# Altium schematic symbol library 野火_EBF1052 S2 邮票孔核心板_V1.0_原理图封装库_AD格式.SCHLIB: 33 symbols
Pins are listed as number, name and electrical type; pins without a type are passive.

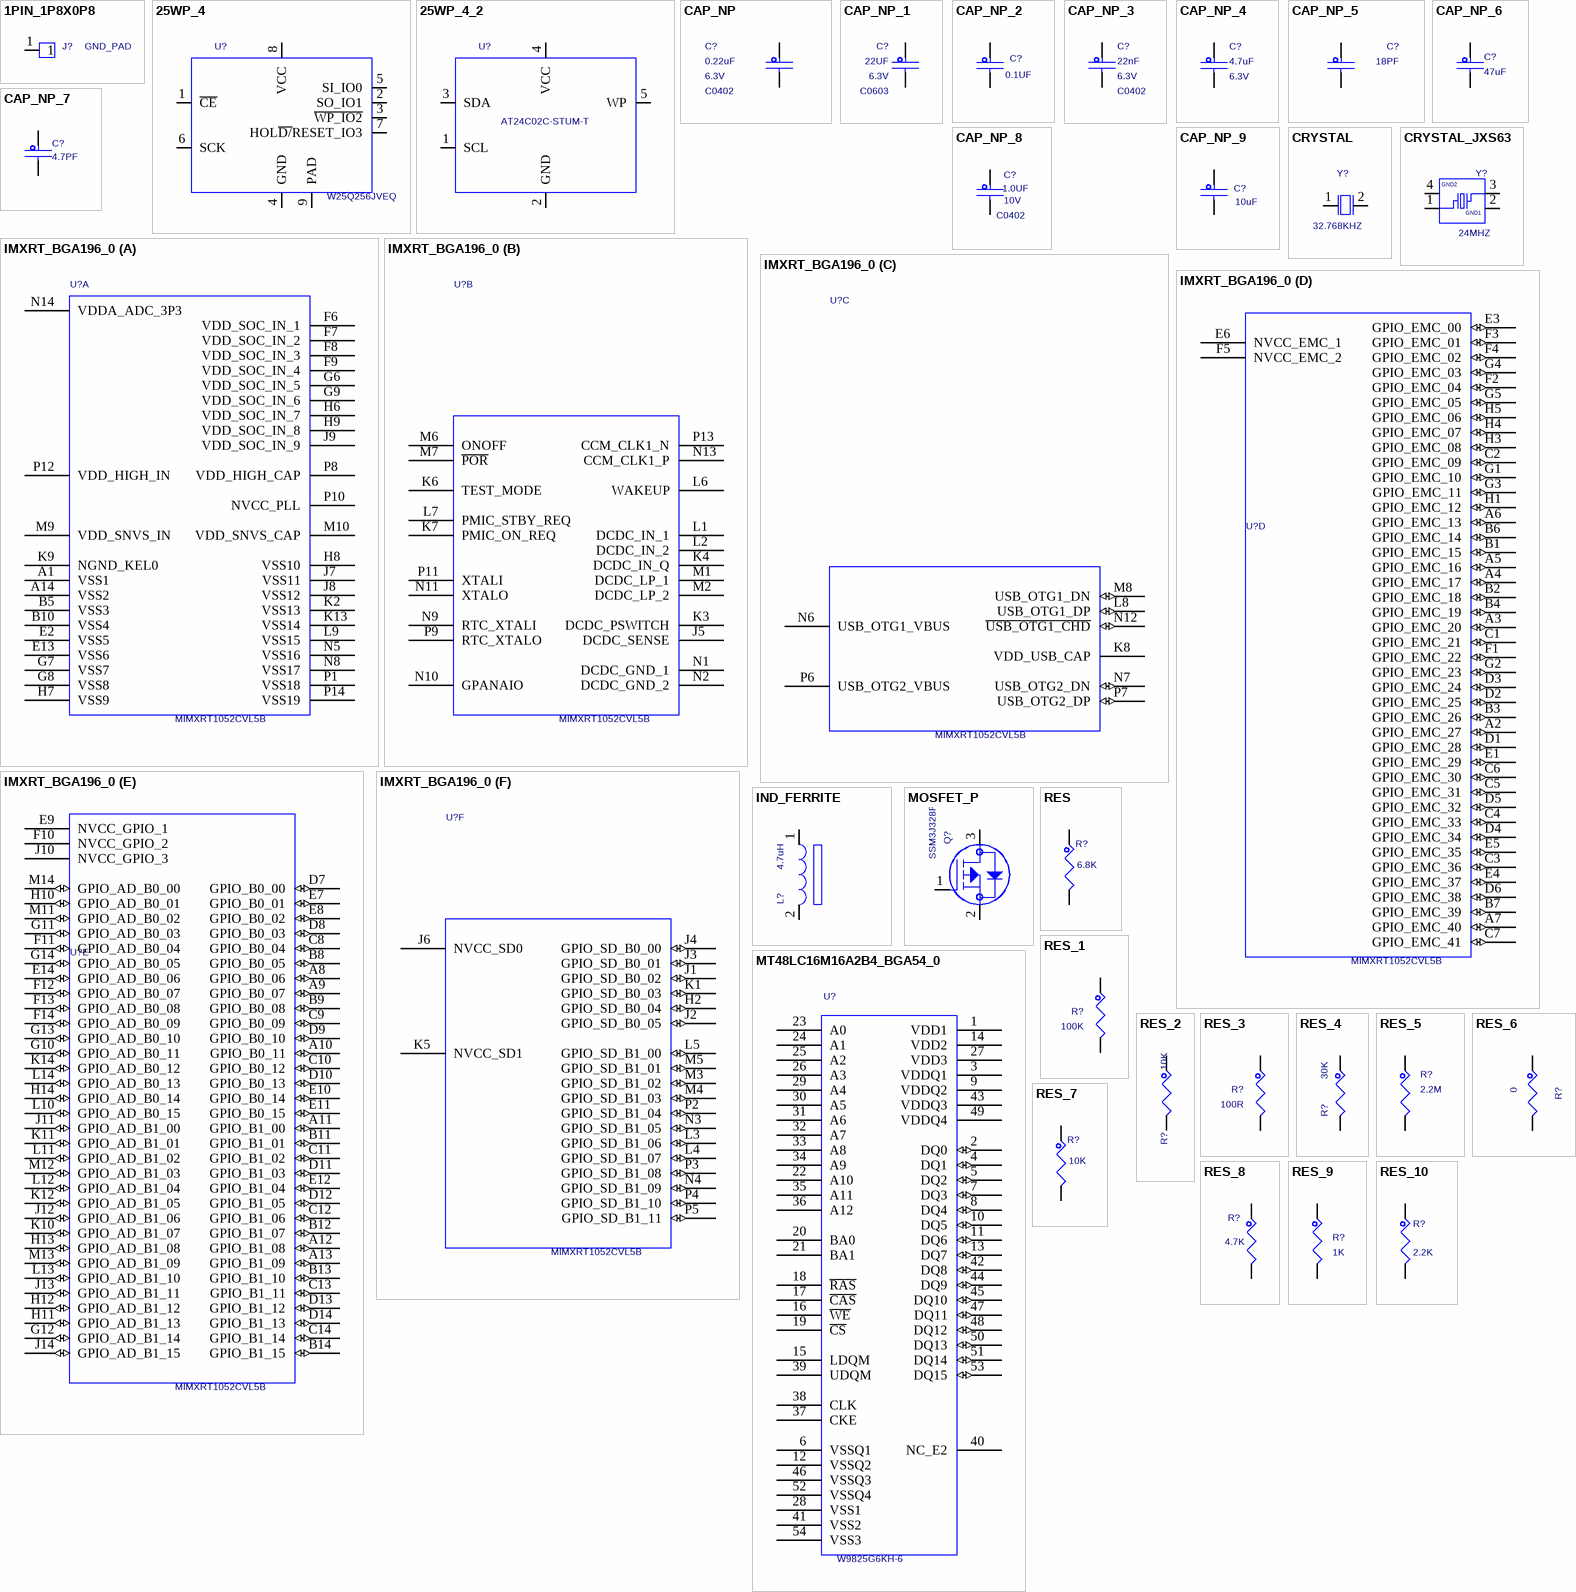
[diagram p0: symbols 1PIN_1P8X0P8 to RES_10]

## 1PIN_1P8X0P8
designator J?  value GND_PAD  (hidden comment: 1PIN_1P8X0P8)
PCB DECAL: PIN-SMD2X2; Source_Path: D:\NXP_RT1050\RT1050_MB_PRO\SCH\LIBRARY1.OLB
footprint PIN-SMD2X2
pins: 1

## 25WP_4
designator U?  value W25Q256JVEQ  (hidden comment: 25WP_4)
IC MEM FLASH QPI 64Mb 1.65-1.95V SOIC8W; PCB DECAL: WSON8_8X6; AGILE_PN: 334-77734; MFG_NAME01: ISSI; MFG_PN01: IS25WP064A-JBLE; Temp_Range: -40C to +105C; CAD_APPROVED: Yes; Source_Path: F:\STM32\F429\SCH\V4\CORE\STM32H743_CORE\STM32H743_CORE.DSN
footprint WSON8_8X6
pins: 1 ~{CE}, 2 SO_IO1, 3 ~{WP_IO2}, 4 GND (power), 5 SI_IO0, 6 SCK, 7 HOL~{D/}RESET_IO3, 8 VCC (power), 9 PAD (power)

## 25WP_4_2
designator U?  value AT24C02C-STUM-T  (hidden comment: 25WP_4_2)
IC MEM FLASH QPI 64Mb 1.65-1.95V SOIC8W; AGILE_PN: 334-77734; MFG_NAME01: ISSI; MFG_PN01: IS25WP064A-JBLE; Temp_Range: -40C to +105C; CAD_APPROVED: Yes; PCB DECAL: SOT23-5; Source_Path: D:\NXP_RT1050\SCH\RT1052B_CORE\IMXRT1052_180613.DSN
footprint SOT23-5
pins: 1 SCL, 2 GND, 3 SDA, 4 VCC (power), 5 WP

## CAP_NP
designator C?  value 0.22uF  VOLTAGE: 6.3V  PCB DECAL: C0402  (hidden comment: CAP_NP)
CAP CER 0.22UF 6.3V 20% X5R 0402; FPLIST: CC0402_25,CC0402_HD,0402_CC; CAD_APPROVED: Yes; MFG_PN01: C0402C224M9PAC; MFG_NAME01: KEMET; AGILE_PN: 150-76271; Source_Path: Q:\ORCADCIS\SYMBOLS\FCL_CAPACITOR.OLB; CLASS: DISCRETE
footprint C0402
pins: 1, 2

## CAP_NP_1
designator C?, comment value 22UF  PCB DECAL: C0603  voltage_rating: 6.3V  (hidden comment: CAP_NP)
CAP CER 22UF 6.3V 20% X5R 0603; FPLIST: CC0603_OV,CC0603,0603_CC; CAD_APPROVED: Yes; MFG_PN01: CL10A226MQ8NRNE; MFG_NAME01: Samsung; AGILE_PN: 150-78467; Source_Path: Q:\ORCADCIS\SYMBOLS\FCL_CAPACITOR.OLB; CLASS: DISCRETE
footprint C0603
pins: 1, 2

## CAP_NP_2
designator C?, comment value 0.1UF  (hidden comment: CAP_NP)
CAP CER 0.1UF 10V 10% X5R 0402; PCB DECAL: C0402; AGILE_PN: 150-75634; MFG_NAME01: KEMET; MFG_PN01: C0402C104K8PAC; CAD_APPROVED: Yes; FPLIST: CC0402_25,CC0402_HD,0402_CC; Source_Path: Q:\ORCADCIS\SYMBOLS\FCL_CAPACITOR.OLB; CLASS: DISCRETE
footprint C0402
pins: 1, 2

## CAP_NP_3
designator C?, comment value 22nF  PCB DECAL: C0402  VOLTAGE: 6.3V  (hidden comment: CAP_NP)
CAP CER 0.22UF 6.3V 20% X5R 0402; AGILE_PN: 150-76271; MFG_NAME01: KEMET; MFG_PN01: C0402C224M9PAC; CAD_APPROVED: Yes; FPLIST: CC0402_25,CC0402_HD,0402_CC; Source_Path: Q:\ORCADCIS\SYMBOLS\FCL_CAPACITOR.OLB; CLASS: DISCRETE
footprint C0402
pins: 1, 2

## CAP_NP_4
designator C?, comment value 4.7uF  voltage_rating: 6.3V  (hidden comment: CAP_NP)
CAP CER 4.7UF 6.3V 20% X5R 0402; FPLIST: CC0402_25,CC0402_HD,0402_CC; CAD_APPROVED: Yes; MFG_PN01: C1005X5R0J475M050BC; MFG_NAME01: TDK; AGILE_PN: 150-78463; PCB DECAL: C0402; Source_Path: Q:\ORCADCIS\SYMBOLS\FCL_CAPACITOR.OLB; CLASS: DISCRETE
footprint C0402
pins: 1, 2

## CAP_NP_5
designator C?, comment value 18PF  (hidden comment: CAP_NP)
CAP CER 18PF 50V 1% C0G 0402; ROOM: ATLAS-AP; PRIORITY_PN: 021-00248; CAD_APPROVED: Yes; MFG_PN01: CC0402FRNPO9BN180; MFG_NAME01: YAGEO; AGILE_PN: 150-76630; FPLIST: CC0402_25,CC0402_HD,0402_CC; PCB DECAL: C0402; Source_Path: Q:\ORCADCIS\SYMBOLS\FCL_CAPACITOR.OLB; CLASS: DISCRETE
footprint C0402
pins: 1, 2

## CAP_NP_6
designator C?, comment value 47uF  (hidden comment: CAP_NP)
CAP CER 33UF 6.3V 20% X5R 1210; FPLIST: CC1210,1210_CC; CAD_APPROVED: Yes; MFG_PN01: GRM32DR60J336ME19L; MFG_NAME01: MURATA; AGILE_PN: 150-76796; PCB DECAL: C0805; Source_Path: Q:\ORCADCIS\SYMBOLS\FCL_CAPACITOR.OLB; CLASS: DISCRETE
footprint C0805
pins: 1, 2

## CAP_NP_7
designator C?, comment value 4.7PF  (hidden comment: CAP_NP)
CAP CER 4.7PF 50V 0.25PF C0G 0402; AGILE_PN: 150-76335; MFG_NAME01: MURATA; MFG_PN01: GRM1555C1H4R7CA01D; CAD_APPROVED: Yes; FPLIST: CC0402_25,CC0402_HD,0402_CC; PCB DECAL: C0402; Source_Path: Q:\ORCADCIS\SYMBOLS\FCL_CAPACITOR.OLB; CLASS: DISCRETE
footprint C0402
pins: 1, 2

## CAP_NP_8
designator C?, comment value 1.0UF  VOLTAGE: 10V  PCB DECAL: C0402  (hidden comment: CAP_NP)
CAP CER 1.0UF 10V 10% X5R 0402; FPLIST: CC0402_25,CC0402_HD,0402_CC; CAD_APPROVED: Yes; MFG_PN01: CC0402KRX5R6BB105; MFG_NAME01: YAGEO AMERICA; AGILE_PN: 150-75772; Source_Path: Q:\ORCADCIS\SYMBOLS\FCL_CAPACITOR.OLB; CLASS: DISCRETE
footprint C0402
pins: 1, 2

## CAP_NP_9
designator C?, comment value 10uF  (hidden comment: CAP_NP)
CAP CER 10UF 10V 10% X5R 0603; PCB DECAL: C0603; FPLIST: CC0603_OV,CC0603,0603_CC; CAD_APPROVED: Yes; MFG_PN01: C1608X5R1A106K; MFG_NAME01: TDK; AGILE_PN: 150-78675; Source_Path: Q:\ORCADCIS\SYMBOLS\FCL_CAPACITOR.OLB; CLASS: DISCRETE
footprint C0603
pins: 1, 2

## CRYSTAL
designator Y?  value 32.768KHZ  (hidden comment: CRYSTAL)
XTAL 32.768KHZ 7PF 20PPM -- SMT; CAD_APPROVED: Yes; MFG_PN01: FC-135 32.7680KA-AG3; MFG_NAME01: EPSON ELECTRONICS; AGILE_PN: 230-78102; PCB DECAL: 3215; Source_Path: Q:\ORCADCIS\SYMBOLS\FCL_XTAL_OSC.OLB; CLASS: IC
footprint 3215
pins: 1, 2

## CRYSTAL_JXS63
designator Y?  value 24MHZ  (hidden comment: CRYSTAL_JXS63)
XTAL 24MHZ -- 30PPM 3.2X2.5MM SMD; CAD_APPROVED: Yes; MFG_PN01: 7V24000002; MFG_NAME01: TXC CORP; AGILE_PN: 230-77452; PCB DECAL: 3225; Source_Path: Q:\ORCADCIS\SYMBOLS\FCL_XTAL_OSC.OLB; CLASS: IC
footprint 3225
pins: 1, 2 GND1 (power), 3, 4 GND2 (power)

## IMXRT_BGA196_0
designator U?  value MIMXRT1052CVL5B  (hidden comment: IMXRT_BGA196_0)
PCB DECAL: BGA196_0P65_10X10MM; Source_Path: D:\NXP_RT1050\SCH\RT1052B_CORE\IMXRT1052_180613.DSN; CLASS: IC; SPLIT_INST: TRUE; SWAP_INFO: (S1+S2+S3+S4+S5+S6)
footprint BGA196_0P65_10X10MM
part A pins: A1 VSS1 (power), A14 VSS2 (power), B5 VSS3 (power), B10 VSS4 (power), E2 VSS5 (power), E13 VSS6 (power), F6 VDD_SOC_IN_1 (power), F7 VDD_SOC_IN_2 (power), F8 VDD_SOC_IN_3 (power), F9 VDD_SOC_IN_4 (power), G6 VDD_SOC_IN_5 (power), G7 VSS7 (power), G8 VSS8 (power), G9 VDD_SOC_IN_6 (power), H6 VDD_SOC_IN_7 (power), H7 VSS9 (power), H8 VSS10 (power), H9 VDD_SOC_IN_8 (power), J7 VSS11 (power), J8 VSS12 (power), J9 VDD_SOC_IN_9 (power), K2 VSS13 (power), K9 NGND_KEL0 (power), K13 VSS14 (power), L9 VSS15 (power), M9 VDD_SNVS_IN (power), M10 VDD_SNVS_CAP (power), N5 VSS16 (power), N8 VSS17 (power), N14 VDDA_ADC_3P3 (power), P1 VSS18 (power), P8 VDD_HIGH_CAP (power), P10 NVCC_PLL (power), P12 VDD_HIGH_IN (power), P14 VSS19 (power)
part B pins: J5 DCDC_SENSE, K3 DCDC_PSWITCH, K4 DCDC_IN_Q, K6 TEST_MODE, K7 PMIC_ON_REQ, L1 DCDC_IN_1, L2 DCDC_IN_2, L6 WAKEUP, L7 PMIC_STBY_REQ, M1 DCDC_LP_1, M2 DCDC_LP_2, M6 ONOFF, M7 ~{POR}, N1 DCDC_GND_1 (power), N2 DCDC_GND_2 (power), N9 RTC_XTALI, N10 GPANAIO, N11 XTALO, N13 CCM_CLK1_P, P9 RTC_XTALO, P11 XTALI, P13 CCM_CLK1_N
part C pins: K8 VDD_USB_CAP (power), L8 USB_OTG1_DP (io), M8 USB_OTG1_DN (io), N6 USB_OTG1_VBUS (power), N7 USB_OTG2_DN (io), N12 ~{USB_OTG1_CHD} (io), P6 USB_OTG2_VBUS (power), P7 USB_OTG2_DP (io)
part D pins: A2 GPIO_EMC_27 (io), A3 GPIO_EMC_20 (io), A4 GPIO_EMC_17 (io), A5 GPIO_EMC_16 (io), A6 GPIO_EMC_13 (io), A7 GPIO_EMC_40 (io), B1 GPIO_EMC_15 (io), B2 GPIO_EMC_18 (io), B3 GPIO_EMC_26 (io), B4 GPIO_EMC_19 (io), B6 GPIO_EMC_14 (io), B7 GPIO_EMC_39 (io), C1 GPIO_EMC_21 (io), C2 GPIO_EMC_09 (io), C3 GPIO_EMC_36 (io), C4 GPIO_EMC_33 (io), C5 GPIO_EMC_31 (io), C6 GPIO_EMC_30 (io), C7 GPIO_EMC_41 (io), D1 GPIO_EMC_28 (io), D2 GPIO_EMC_25 (io), D3 GPIO_EMC_24 (io), D4 GPIO_EMC_34 (io), D5 GPIO_EMC_32 (io), D6 GPIO_EMC_38 (io), E1 GPIO_EMC_29 (io), E3 GPIO_EMC_00 (io), E4 GPIO_EMC_37 (io), E5 GPIO_EMC_35 (io), E6 NVCC_EMC_1 (power), F1 GPIO_EMC_22 (io), F2 GPIO_EMC_04 (io), F3 GPIO_EMC_01 (io), F4 GPIO_EMC_02 (io), F5 NVCC_EMC_2 (power), G1 GPIO_EMC_10 (io), G2 GPIO_EMC_23 (io), G3 GPIO_EMC_11 (io), G4 GPIO_EMC_03 (io), G5 GPIO_EMC_05 (io), H1 GPIO_EMC_12 (io), H3 GPIO_EMC_08 (io), H4 GPIO_EMC_07 (io), H5 GPIO_EMC_06 (io)
part E pins: A8 GPIO_B0_06 (io), A9 GPIO_B0_07 (io), A10 GPIO_B0_11 (io), A11 GPIO_B1_00 (io), A12 GPIO_B1_08 (io), A13 GPIO_B1_09 (io), B8 GPIO_B0_05 (io), B9 GPIO_B0_08 (io), B11 GPIO_B1_01 (io), B12 GPIO_B1_07 (io), B13 GPIO_B1_10 (io), B14 GPIO_B1_15 (io), C8 GPIO_B0_04 (io), C9 GPIO_B0_09 (io), C10 GPIO_B0_12 (io), C11 GPIO_B1_02 (io), C12 GPIO_B1_06 (io), C13 GPIO_B1_11 (io), C14 GPIO_B1_14 (io), D7 GPIO_B0_00 (io), D8 GPIO_B0_03 (io), D9 GPIO_B0_10 (io), D10 GPIO_B0_13 (io), D11 GPIO_B1_03 (io), D12 GPIO_B1_05 (io), D13 GPIO_B1_12 (io), D14 GPIO_B1_13 (io), E7 GPIO_B0_01 (io), E8 GPIO_B0_02 (io), E9 NVCC_GPIO_1 (power), E10 GPIO_B0_14 (io), E11 GPIO_B0_15 (io), E12 GPIO_B1_04 (io), E14 GPIO_AD_B0_06 (io), F10 NVCC_GPIO_2 (power), F11 GPIO_AD_B0_04 (io), F12 GPIO_AD_B0_07 (io), F13 GPIO_AD_B0_08 (io), F14 GPIO_AD_B0_09 (io), G10 GPIO_AD_B0_11 (io), G11 GPIO_AD_B0_03 (io), G12 GPIO_AD_B1_14 (io), G13 GPIO_AD_B0_10 (io), G14 GPIO_AD_B0_05 (io), H10 GPIO_AD_B0_01 (io), H11 GPIO_AD_B1_13 (io), H12 GPIO_AD_B1_12 (io), H13 GPIO_AD_B1_08 (io), H14 GPIO_AD_B0_14 (io), J10 NVCC_GPIO_3 (power), J11 GPIO_AD_B1_00 (io), J12 GPIO_AD_B1_06 (io), J13 GPIO_AD_B1_11 (io), J14 GPIO_AD_B1_15 (io), K10 GPIO_AD_B1_07 (io), K11 GPIO_AD_B1_01 (io), K12 GPIO_AD_B1_05 (io), K14 GPIO_AD_B0_12 (io), L10 GPIO_AD_B0_15 (io), L11 GPIO_AD_B1_02 (io), L12 GPIO_AD_B1_04 (io), L13 GPIO_AD_B1_10 (io), L14 GPIO_AD_B0_13 (io), M11 GPIO_AD_B0_02 (io), M12 GPIO_AD_B1_03 (io), M13 GPIO_AD_B1_09 (io), M14 GPIO_AD_B0_00 (io)
part F pins: H2 GPIO_SD_B0_04 (io), J1 GPIO_SD_B0_02 (io), J2 GPIO_SD_B0_05 (io), J3 GPIO_SD_B0_01 (io), J4 GPIO_SD_B0_00 (io), J6 NVCC_SD0 (power), K1 GPIO_SD_B0_03 (io), K5 NVCC_SD1 (power), L3 GPIO_SD_B1_06 (io), L4 GPIO_SD_B1_07 (io), L5 GPIO_SD_B1_00 (io), M3 GPIO_SD_B1_02 (io), M4 GPIO_SD_B1_03 (io), M5 GPIO_SD_B1_01 (io), N3 GPIO_SD_B1_05 (io), N4 GPIO_SD_B1_09 (io), P2 GPIO_SD_B1_04 (io), P3 GPIO_SD_B1_08 (io), P4 GPIO_SD_B1_10 (io), P5 GPIO_SD_B1_11 (io)

## IND_FERRITE
designator L?  value 4.7uH  (hidden comment: IND_FERRITE)
IND WW FER 4.7uH@1MHz 1.4A 20% 4012; CAD_APPROVED: Yes; Temp_Range: -40C to +105C; MFG_PN01: VLS4012ET-4R7M; MFG_NAME01: TDK; AGILE_PN: 180-78674; PCB DECAL: L4018; Source_Path: Q:\ORCADCIS\SYMBOLS\FCL_INDUCTOR.OLB; CLASS: DISCRETE
footprint L4018
pins: 1, 2

## MOSFET_P
designator Q?  value SSM3J328R  (hidden comment: MOSFET_P)
TRAN PMOS PWR 12V 4.3A SOT23; CAD_APPROVED: Yes; MFG_PN01: IRLML6401TRPBF; MFG_NAME01: INTERNATIONAL RECTIFIER; AGILE_PN: 480-77718; Source_Path: Q:\ORCADCIS\SYMBOLS\FCL_SEMICONDUCTOR.OLB; CLASS: IC
footprint SOT23
pins: 1 GATE, 2 SOURCE, 3 DRAIN

## MT48LC16M16A2B4_BGA54_0
designator U?  value W9825G6KH-6  (hidden comment: MT48LC16M16A2B4_BGA54_0)
IC MEM SDRAM 16MX16 6NS 3.3V VFBGA54; CAD_APPROVED: Yes; MFG_PN01: MT48LC16M16A2B4-6A IT:G; MFG_NAME01: MICRON; AGILE_PN: 334-77696; PCB DECAL: TSOP54; Source_Path: H:\NXP_RT1050\SCH\IMXRT1052.DSN
footprint TSOP54
pins: 1 VDD1 (power), 2 DQ0 (io), 3 VDDQ1 (power), 4 DQ1 (io), 5 DQ2 (io), 6 VSSQ1 (power), 7 DQ3 (io), 8 DQ4 (io), 9 VDDQ2 (power), 10 DQ5 (io), 11 DQ6 (io), 12 VSSQ2 (power), 13 DQ7 (io), 14 VDD2 (power), 15 LDQM, 16 ~{WE}, 17 ~{CAS}, 18 ~{RAS}, 19 ~{CS}, 20 BA0, 21 BA1, 22 A10, 23 A0, 24 A1, 25 A2, 26 A3, 27 VDD3 (power), 28 VSS1 (power), 29 A4, 30 A5, 31 A6, 32 A7, 33 A8, 34 A9, 35 A11, 36 A12, 37 CKE, 38 CLK, 39 UDQM, 40 NC_E2, 41 VSS2 (power), 42 DQ8 (io), 43 VDDQ3 (power), 44 DQ9 (io), 45 DQ10 (io), 46 VSSQ3 (power), 47 DQ11 (io), 48 DQ12 (io), 49 VDDQ4 (power), 50 DQ13 (io), 51 DQ14 (io), 52 VSSQ4 (power), 53 DQ15 (io), 54 VSS3 (power)

## RES
designator R?  value 6.8K  (hidden comment: RES)
RES MF 4.7K 1/16W 5% 0402; FPLIST: RC0402_25,RC0402_HD,0402_CC; CAD_APPROVED: Yes; MFG_PN01: RK73B1ETTP472J; MFG_NAME01: KOA SPEER; AGILE_PN: 470-75626; PCB DECAL: R0402; Source_Path: Q:\ORCADCIS\SYMBOLS\FCL_RESISTOR.OLB; CLASS: DISCRETE
footprint R0402
pins: 1, 2

## RES_1
designator R?, comment value 100K  (hidden comment: RES)
RES MF 10K 1/16W 5% 0402; PCB DECAL: R0402; FPLIST: RC0402_25,RC0402_HD,0402_CC; CAD_APPROVED: Yes; MFG_PN01: CRCW040210K0JNED; MFG_NAME01: VISHAY INTERTECHNOLOGY; AGILE_PN: 470-75557; Source_Path: Q:\ORCADCIS\SYMBOLS\FCL_RESISTOR.OLB; CLASS: DISCRETE
footprint R0402
pins: 1, 2

## RES_2
designator R?, comment value 10K  (hidden comment: RES)
RES MF 10K 1/16W 5% 0402; AGILE_PN: 470-75557; MFG_NAME01: VISHAY INTERTECHNOLOGY; MFG_PN01: CRCW040210K0JNED; CAD_APPROVED: Yes; FPLIST: RC0402_25,RC0402_HD,0402_CC; PCB DECAL: R0402; Source_Path: Q:\ORCADCIS\SYMBOLS\FCL_RESISTOR.OLB; CLASS: DISCRETE
footprint R0402
pins: 1, 2

## RES_3
designator R?, comment value 100R  (hidden comment: RES)
RES MF 10K 1/16W 5% 0402; PCB DECAL: R0402; FPLIST: RC0402_25,RC0402_HD,0402_CC; CAD_APPROVED: Yes; MFG_PN01: CRCW040210K0JNED; MFG_NAME01: VISHAY INTERTECHNOLOGY; AGILE_PN: 470-75557; Source_Path: Q:\ORCADCIS\SYMBOLS\FCL_RESISTOR.OLB; CLASS: DISCRETE
footprint R0402
pins: 1, 2

## RES_4
designator R?, comment value 30K  (hidden comment: RES)
RES MF ZERO OHM 1/16W 5% 0402; FPLIST: RC0402_25,RC0402_HD,RC0402_X2,0402_CC; CAD_APPROVED: Yes; MFG_PN01: MCR01MZPJ000; MFG_NAME01: ROHM; AGILE_PN: 470-75394; PCB DECAL: R0402; Source_Path: Q:\ORCADCIS\SYMBOLS\FCL_RESISTOR.OLB; CLASS: DISCRETE
footprint R0402
pins: 1, 2

## RES_5
designator R?, comment value 2.2M  (hidden comment: RES)
RES MF 2.2M  1/16W 1% 0402; FPLIST: RC0402_25,RC0402_HD,0402_CC; CAD_APPROVED: Yes; MFG_PN01: RK73H1ETTP2204F; MFG_NAME01: KOA SPEER; AGILE_PN: 470-31210; PCB DECAL: R0402; Source_Path: Q:\ORCADCIS\SYMBOLS\FCL_RESISTOR.OLB; CLASS: DISCRETE
footprint R0402
pins: 1, 2

## RES_6
designator R?, comment value 0  (hidden comment: RES)
RES MF ZERO OHM 1/16W 5% 0402; FPLIST: RC0402_25,RC0402_HD,RC0402_X2,0402_CC; CAD_APPROVED: Yes; MFG_PN01: MCR01MZPJ000; MFG_NAME01: ROHM; AGILE_PN: 470-75394; PCB DECAL: R0402; Source_Path: Q:\ORCADCIS\SYMBOLS\FCL_RESISTOR.OLB; CLASS: DISCRETE
footprint R0402
pins: 1, 2

## RES_7
designator R?, comment value 10K  (hidden comment: RES)
RES MF 4.7K 1/16W 5% 0402; FPLIST: RC0402_25,RC0402_HD,0402_CC; CAD_APPROVED: Yes; MFG_PN01: RK73B1ETTP472J; MFG_NAME01: KOA SPEER; AGILE_PN: 470-75626; PCB DECAL: R0402; Source_Path: Q:\ORCADCIS\SYMBOLS\FCL_RESISTOR.OLB; CLASS: DISCRETE
footprint R0402
pins: 1, 2

## RES_8
designator R?, comment value 4.7K  (hidden comment: RES)
RES MF 4.7K 1/16W 5% 0402; PCB DECAL: R0402; FPLIST: RC0402_25,RC0402_HD,0402_CC; CAD_APPROVED: Yes; MFG_PN01: RK73B1ETTP472J; MFG_NAME01: KOA SPEER; AGILE_PN: 470-75626; Source_Path: Q:\ORCADCIS\SYMBOLS\FCL_RESISTOR.OLB; CLASS: DISCRETE
footprint R0402
pins: 1, 2

## RES_9
designator R?, comment value 1K  (hidden comment: RES)
RES MF 1.0K 1/16W 5% 0402; PCB DECAL: R0402; FPLIST: RC0402_25,RC0402_HD,RC0402_X2,0402_CC; CAD_APPROVED: Yes; MFG_PN01: CRCW04021K00JNED; MFG_NAME01: VISHAY INTERTECHNOLOGY; AGILE_PN: 470-75555; Source_Path: Q:\ORCADCIS\SYMBOLS\FCL_RESISTOR.OLB; CLASS: DISCRETE
footprint R0402
pins: 1, 2

## RES_10
designator R?, comment value 2.2K  (hidden comment: RES)
RES MF 10K 1/16W 5% 0402; AGILE_PN: 470-75557; MFG_NAME01: VISHAY INTERTECHNOLOGY; MFG_PN01: CRCW040210K0JNED; CAD_APPROVED: Yes; FPLIST: RC0402_25,RC0402_HD,0402_CC; PCB DECAL: R0402; Source_Path: Q:\ORCADCIS\SYMBOLS\FCL_RESISTOR.OLB; CLASS: DISCRETE
footprint R0402
pins: 1, 2

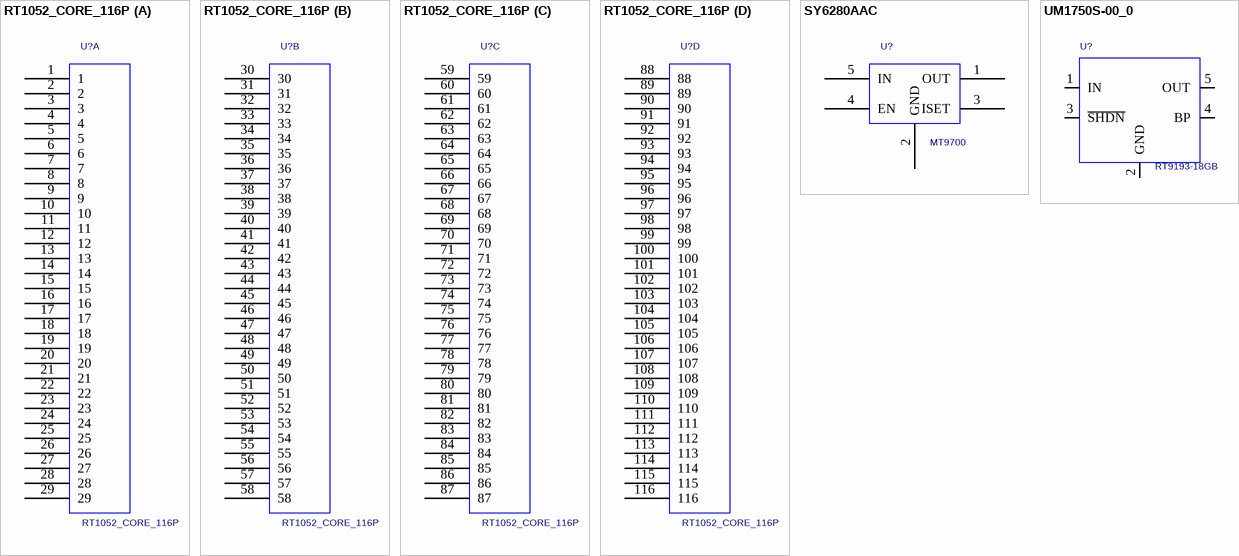
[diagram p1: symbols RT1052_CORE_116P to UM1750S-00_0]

## RT1052_CORE_116P
designator U?
PCB DECAL: RT1052_CORE_116P_38X38; Source_Path: D:\NXP_RT1050\SCH\SCHLIB\YHSCHLIB.OLB
footprint RT1052_CORE_116P_38X38
part A pins: 1, 2, 3, 4, 5, 6, 7, 8, 9, 10, 11, 12, 13, 14, 15, 16, 17, 18, 19, 20, 21, 22, 23, 24, 25, 26, 27, 28, 29
part B pins: 30, 31, 32, 33, 34, 35, 36, 37, 38, 39, 40, 41, 42, 43, 44, 45, 46, 47, 48, 49, 50, 51, 52, 53, 54, 55, 56, 57, 58
part C pins: 59, 60, 61, 62, 63, 64, 65, 66, 67, 68, 69, 70, 71, 72, 73, 74, 75, 76, 77, 78, 79, 80, 81, 82, 83, 84, 85, 86, 87
part D pins: 88, 89, 90, 91, 92, 93, 94, 95, 96, 97, 98, 99, 100, 101, 102, 103, 104, 105, 106, 107, 108, 109, 110, 111, 112, 113, 114, 115, 116

## SY6280AAC
designator U?  value MT9700  (hidden comment: SY6280AAC)
PCB DECAL: SOT23-5; Source_Path: G:\开发板代码\郭老师资料\IMX6资料\原理图\SABRESDB_DESIGNFILES\DEVELOP\LIBRARY1.OLB
footprint SOT23-5
pins: 1 OUT, 2 GND, 3 ISET, 4 EN, 5 IN

## UM1750S-00_0
designator U?  value RT9193-18GB  (hidden comment: UM1750S-00_0)
IC VREG LDO ADJ 1-5V 350mA 2.5-6V SOT23-5; CAD_APPROVED: Yes; MFG_NAME01: Union Semiconductor, Inc; AGILE_PN: 315-80554; Source_Path: H:\NXP_RT1050\SCH\IMXRT1052.DSN
footprint SOT23-5
pins: 1 IN (power), 2 GND (power), 3 ~{SHDN}, 4 BP, 5 OUT (power)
